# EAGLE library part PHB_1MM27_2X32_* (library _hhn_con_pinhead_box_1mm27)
Pin Header Box-Type, 1.27mm/0.5"/50mil Pitch, 2x32 Circuits Note: see library description for an important note about THT-version
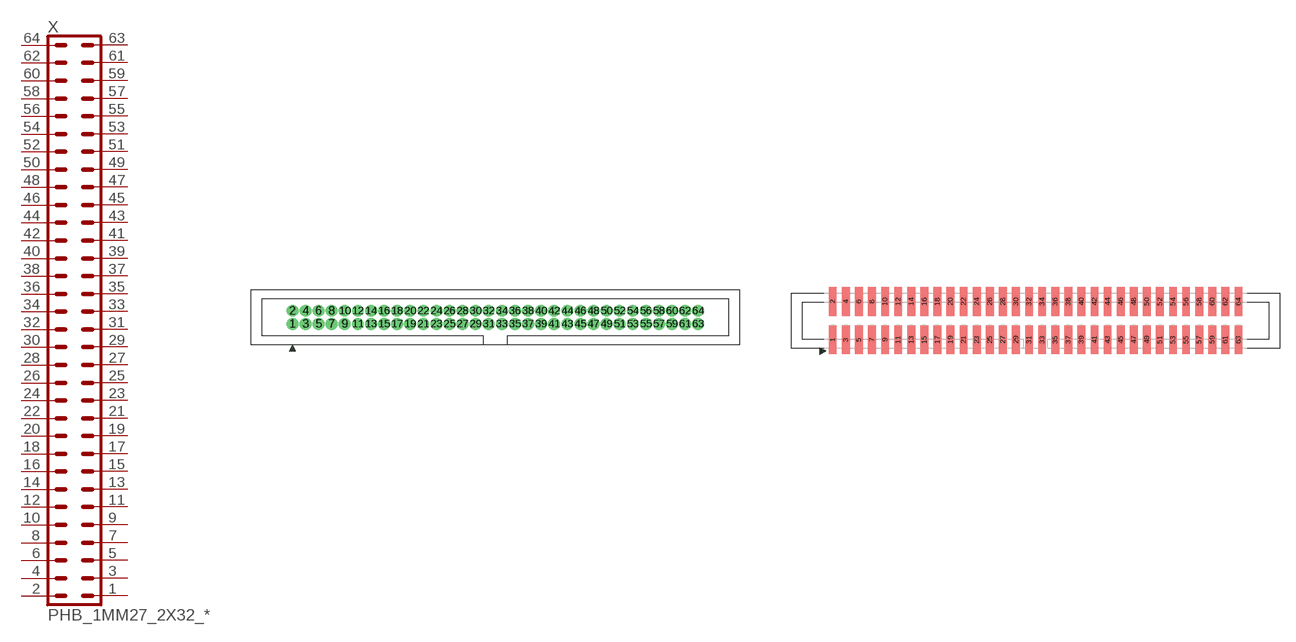
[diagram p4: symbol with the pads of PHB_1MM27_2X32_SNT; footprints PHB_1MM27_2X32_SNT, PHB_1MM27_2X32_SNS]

Designator prefix X

## PHB_1MM27_2X32_SNT  [PHB_1MM27_2X32_SNT]
1  1  pas
2  2  pas
3  3  pas
4  4  pas
5  5  pas
6  6  pas
7  7  pas
8  8  pas
9  9  pas
10  10  pas
11  11  pas
12  12  pas
13  13  pas
14  14  pas
15  15  pas
16  16  pas
17  17  pas
18  18  pas
19  19  pas
20  20  pas
21  21  pas
22  22  pas
23  23  pas
24  24  pas
25  25  pas
26  26  pas
27  27  pas
28  28  pas
29  29  pas
30  30  pas
31  31  pas
32  32  pas
33  33  pas
34  34  pas
35  35  pas
36  36  pas
37  37  pas
38  38  pas
39  39  pas
40  40  pas
41  41  pas
42  42  pas
43  43  pas
44  44  pas
45  45  pas
46  46  pas
47  47  pas
48  48  pas
49  49  pas
50  50  pas
51  51  pas
52  52  pas
53  53  pas
54  54  pas
55  55  pas
56  56  pas
57  57  pas
58  58  pas
59  59  pas
60  60  pas
61  61  pas
62  62  pas
63  63  pas
64  64  pas

## PHB_1MM27_2X32_SNS  [PHB_1MM27_2X32_SNS]
Pads as for PHB_1MM27_2X32_SNT

## Footprint PHB_1MM27_2X32_SNT (pad centres in mm)
Pin Header Box-Type, 1.27mm Pitch, 2x32 circuits, Straight, No Locking, THT Important Note: Diameter in this lbr is set to a specific value (NOT 'auto' = 0), this is ignored by actual eagle versions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
drill 0.65 pad 1 round: 1 -19.685,-0.635; 2 -19.685,0.635; 3 -18.415,-0.635; 4 -18.415,0.635; 5 -17.145,-0.635; 6 -17.145,0.635; 7 -15.875,-0.635; 8 -15.875,0.635; 9 -14.605,-0.635; 10 -14.605,0.635; 11 -13.335,-0.635; 12 -13.335,0.635; 13 -12.065,-0.635; 14 -12.065,0.635; 15 -10.795,-0.635; 16 -10.795,0.635; 17 -9.525,-0.635; 18 -9.525,0.635; 19 -8.255,-0.635; 20 -8.255,0.635; 21 -6.985,-0.635; 22 -6.985,0.635; 23 -5.715,-0.635; 24 -5.715,0.635; 25 -4.445,-0.635; 26 -4.445,0.635; 27 -3.175,-0.635; 28 -3.175,0.635; 29 -1.905,-0.635; 30 -1.905,0.635; 31 -0.635,-0.635; 32 -0.635,0.635; 33 0.635,-0.635; 34 0.635,0.635; 35 1.905,-0.635; 36 1.905,0.635; 37 3.175,-0.635; 38 3.175,0.635; 39 4.445,-0.635; 40 4.445,0.635; 41 5.715,-0.635; 42 5.715,0.635; 43 6.985,-0.635; 44 6.985,0.635; 45 8.255,-0.635; 46 8.255,0.635; 47 9.525,-0.635; 48 9.525,0.635; 49 10.795,-0.635; 50 10.795,0.635; 51 12.065,-0.635; 52 12.065,0.635; 53 13.335,-0.635; 54 13.335,0.635; 55 14.605,-0.635; 56 14.605,0.635; 57 15.875,-0.635; 58 15.875,0.635; 59 17.145,-0.635; 60 17.145,0.635; 61 18.415,-0.635; 62 18.415,0.635; 63 19.685,-0.635; 64 19.685,0.635

## Footprint PHB_1MM27_2X32_SNS (pad centres in mm)
Pin Header Box-Type, 1.27mm Pitch, 2x32 circuits, Straight, No Locking, SMT
smd 0.76 x 2.8: 1 -19.685,-1.85; 2 -19.685,1.85; 3 -18.415,-1.85; 4 -18.415,1.85; 5 -17.145,-1.85; 6 -17.145,1.85; 7 -15.875,-1.85; 8 -15.875,1.85; 9 -14.605,-1.85; 10 -14.605,1.85; 11 -13.335,-1.85; 12 -13.335,1.85; 13 -12.065,-1.85; 14 -12.065,1.85; 15 -10.795,-1.85; 16 -10.795,1.85; 17 -9.525,-1.85; 18 -9.525,1.85; 19 -8.255,-1.85; 20 -8.255,1.85; 21 -6.985,-1.85; 22 -6.985,1.85; 23 -5.715,-1.85; 24 -5.715,1.85; 25 -4.445,-1.85; 26 -4.445,1.85; 27 -3.175,-1.85; 28 -3.175,1.85; 29 -1.905,-1.85; 30 -1.905,1.85; 31 -0.635,-1.85; 32 -0.635,1.85; 33 0.635,-1.85; 34 0.635,1.85; 35 1.905,-1.85; 36 1.905,1.85; 37 3.175,-1.85; 38 3.175,1.85; 39 4.445,-1.85; 40 4.445,1.85; 41 5.715,-1.85; 42 5.715,1.85; 43 6.985,-1.85; 44 6.985,1.85; 45 8.255,-1.85; 46 8.255,1.85; 47 9.525,-1.85; 48 9.525,1.85; 49 10.795,-1.85; 50 10.795,1.85; 51 12.065,-1.85; 52 12.065,1.85; 53 13.335,-1.85; 54 13.335,1.85; 55 14.605,-1.85; 56 14.605,1.85; 57 15.875,-1.85; 58 15.875,1.85; 59 17.145,-1.85; 60 17.145,1.85; 61 18.415,-1.85; 62 18.415,1.85; 63 19.685,-1.85; 64 19.685,1.85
